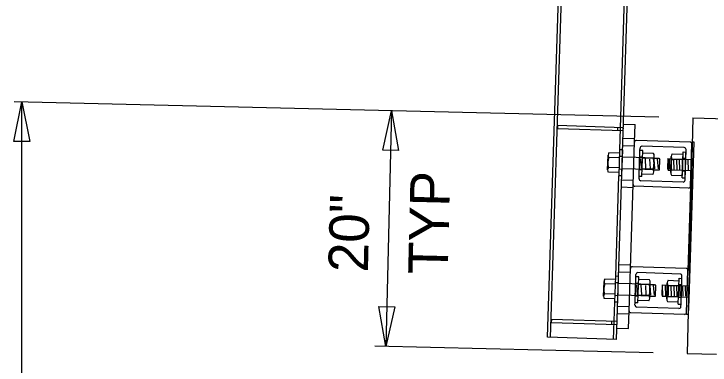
# Model space of a CAD drawing. Extents: x -86 to 68, y -5 to 62.
# Drawn here: x 7.703 to 12.621, y 25.889 to 28.371 of the extents above; entities that cross this region are included whole.
import ezdxf

# ---------------------------------------------------------------- set-up
doc = ezdxf.new("R2010")
doc.units = 0
for name, color, linetype in [('BR_P_Gen_Text', 7, 'Continuous'), ('BR_P_Rail_Hidden', 7, 'Continuous'), ('BR_P_Rail_Object', 7, 'Continuous'), ('BR_P_Slab_Object', 7, 'Continuous'), ('TX_P_1', 7, 'Continuous')]:
    doc.layers.add(name, color=color, linetype=linetype)

msp = doc.modelspace()

# ---------------------------------------------------------------- linework, layer by layer
at = {"layer": 'BR_P_Gen_Text'}
for points in [[(7.8153, 27.4694), (7.7033, 27.4694), (7.7593, 27.7494)], [(10.4206, 27.4054), (10.3087, 27.4081), (10.3714, 27.6867)], [(10.2821, 26.3022), (10.3941, 26.2995), (10.3314, 26.021)]]:
    msp.add_lwpolyline(points, close=True, dxfattribs=at)
at = {"layer": 'BR_P_Rail_Hidden'}
for p, q in [((12.0099, 27.5921), (12.0911, 27.5895)), ((12.0871, 27.4643), (12.0911, 27.5895)), ((12.0878, 27.488), (12.0066, 27.4906)), ((12.0862, 27.4372), (12.005, 27.4398)), ((12.0025, 27.3637), (11.9822, 27.3643)), ((12.098, 27.3564), (12.0024, 27.3595)), ((12.2267, 27.3523), (12.098, 27.3564)), ((12.1216, 27.2726), (12.1242, 27.3556)), ((12.1447, 27.3591), (12.1244, 27.3598)), ((12.1361, 27.2798), (12.1325, 27.3477)), ((12.1677, 27.2788), (12.1641, 27.3467)), ((12.1993, 27.2778), (12.1957, 27.3456)), ((12.4492, 27.3494), (12.4289, 27.35)), ((11.9996, 27.2723), (11.9793, 27.273)), ((12.0953, 27.2734), (11.9998, 27.2765)), ((12.2241, 27.2693), (12.0953, 27.2734)), ((12.1417, 27.2678), (12.1214, 27.2684)), ((12.4463, 27.258), (12.426, 27.2587)), ((12.0784, 27.1936), (11.9972, 27.1962)), ((12.0585, 26.571), (12.0775, 27.1665)), ((12.0768, 27.1428), (11.9956, 27.1454)), ((12.0592, 26.5947), (11.978, 26.5973)), ((12.0576, 26.5439), (11.9764, 26.5465)), ((11.974, 26.4704), (11.9537, 26.471)), ((12.0694, 26.4631), (11.9738, 26.4662)), ((12.1981, 26.459), (12.0694, 26.4631)), ((12.093, 26.3793), (12.0956, 26.4623)), ((12.1161, 26.4658), (12.0958, 26.4665)), ((12.1076, 26.3865), (12.1039, 26.4544)), ((12.1391, 26.3855), (12.1355, 26.4534)), ((12.1707, 26.3845), (12.1671, 26.4524)), ((12.4206, 26.4561), (12.4003, 26.4567)), ((11.971, 26.379), (11.9507, 26.3797)), ((12.0668, 26.3801), (11.9712, 26.3832)), ((12.1955, 26.376), (12.0668, 26.3801)), ((12.1132, 26.3745), (12.0928, 26.3751)), ((12.4177, 26.3647), (12.3974, 26.3654)), ((12.0498, 26.3003), (11.9686, 26.3029)), ((12.0449, 26.148), (12.0489, 26.2732)), ((12.0482, 26.2495), (11.967, 26.2521)), ((11.9637, 26.1506), (12.0449, 26.148))]:
    msp.add_line(p, q, dxfattribs=at)
at = {"layer": 'BR_P_Rail_Object'}
for p, q in [((11.4739, 26.085), (11.6142, 30.4703)), ((11.9829, 27.41), (12.0804, 30.4553)), ((11.495, 26.0843), (11.6171, 29.9011)), ((11.9611, 26.0694), (12.0435, 28.6444)), ((11.9684, 27.568), (11.9678, 27.5477)), ((12.0775, 27.1665), (12.0871, 27.4643)), ((12.48, 27.4652), (12.101, 27.4774)), ((12.4731, 26.3515), (12.5088, 27.4643)), ((12.4836, 27.1533), (12.4931, 27.4513)), ((12.4935, 27.4648), (12.4931, 27.4513)), ((12.5088, 27.4643), (12.4935, 27.4648)), ((11.9779, 27.2273), (11.9837, 27.41)), ((12.004, 27.4093), (11.9837, 27.41)), ((11.9982, 27.2266), (12.004, 27.4093)), ((12.12, 27.2227), (12.1258, 27.4055)), ((12.1258, 27.4055), (12.1264, 27.4224)), ((12.1461, 27.4048), (12.1258, 27.4055)), ((12.4381, 27.4259), (12.1403, 27.4355)), ((12.1403, 27.2221), (12.1461, 27.4048)), ((12.4245, 27.213), (12.4304, 27.3957)), ((12.4304, 27.3957), (12.4507, 27.3951)), ((12.4443, 27.1954), (12.4512, 27.412)), ((12.4448, 27.2123), (12.4507, 27.3951)), ((11.8976, 27.2689), (11.9009, 27.3736)), ((11.9819, 27.3547), (11.9058, 27.3572)), ((11.983, 27.3872), (11.9069, 27.3896)), ((12.2212, 27.3482), (12.1444, 27.3507)), ((12.2224, 27.3854), (12.1456, 27.3879)), ((12.2236, 27.255), (12.2272, 27.3666)), ((12.2267, 27.3523), (12.2584, 27.3513)), ((12.2309, 27.2768), (12.2273, 27.3446)), ((12.2584, 27.3513), (12.266, 27.339)), ((12.3221, 27.3484), (12.32, 27.2803)), ((12.3221, 27.3484), (12.3246, 27.267)), ((12.3221, 27.3484), (12.3465, 27.3476)), ((12.3435, 27.2511), (12.347, 27.3628)), ((12.3465, 27.3476), (12.5049, 27.3425)), ((12.353, 27.3812), (12.4298, 27.3788)), ((12.4298, 27.3788), (12.425, 27.2299)), ((12.2571, 27.2759), (12.2498, 27.3439)), ((12.2637, 27.268), (12.266, 27.339)), ((12.3325, 27.3413), (12.3346, 27.2734)), ((12.3519, 27.344), (12.4286, 27.3416)), ((12.363, 27.3403), (12.365, 27.2725)), ((12.3833, 27.3396), (12.3853, 27.2718)), ((12.4036, 27.339), (12.4056, 27.2712)), ((12.4239, 27.3383), (12.4259, 27.2705)), ((12.4442, 27.3377), (12.4462, 27.2699)), ((12.4645, 27.337), (12.4665, 27.2692)), ((12.4848, 27.3364), (12.4868, 27.2686)), ((11.9786, 27.2501), (11.9025, 27.2525)), ((11.9796, 27.2826), (11.9035, 27.285)), ((12.2188, 27.2738), (12.142, 27.2762)), ((12.2241, 27.2693), (12.2637, 27.268)), ((12.32, 27.2803), (12.3246, 27.267)), ((12.3246, 27.267), (12.3439, 27.2664)), ((12.5023, 27.2613), (12.3439, 27.2664)), ((12.3495, 27.2696), (12.4262, 27.2671)), ((11.9543, 26.5167), (11.977, 27.2273)), ((11.9982, 27.2266), (11.9779, 27.2273)), ((12.1194, 27.2058), (12.12, 27.2227)), ((12.1403, 27.2221), (12.12, 27.2227)), ((12.2176, 27.2365), (12.1408, 27.239)), ((12.3483, 27.2324), (12.425, 27.2299)), ((12.4245, 27.213), (12.4448, 27.2123)), ((12.4696, 27.1404), (12.0906, 27.1525)), ((12.4303, 27.1823), (12.1325, 27.1918)), ((12.4836, 27.1535), (12.4645, 26.558)), ((12.0489, 26.2732), (12.0585, 26.571)), ((12.4514, 26.572), (12.0724, 26.5841)), ((12.455, 26.2602), (12.4645, 26.558)), ((11.9493, 26.334), (11.9551, 26.5167)), ((11.9754, 26.5161), (11.9551, 26.5167)), ((11.9696, 26.3333), (11.9754, 26.5161)), ((12.0914, 26.3294), (12.0972, 26.5122)), ((12.0972, 26.5122), (12.0978, 26.5291)), ((12.1175, 26.5115), (12.0972, 26.5122)), ((12.4095, 26.5326), (12.1117, 26.5422)), ((12.1117, 26.3288), (12.1175, 26.5115)), ((12.4221, 26.5018), (12.4226, 26.5187)), ((11.869, 26.3756), (11.8723, 26.4803)), ((11.9534, 26.4614), (11.8772, 26.4639)), ((11.9544, 26.4939), (11.8783, 26.4963)), ((12.1938, 26.4921), (12.117, 26.4946)), ((12.195, 26.3617), (12.1986, 26.4733)), ((12.1981, 26.459), (12.2298, 26.458)), ((12.3149, 26.3579), (12.3184, 26.4695)), ((12.3245, 26.488), (12.4012, 26.4855)), ((12.3959, 26.3197), (12.4018, 26.5024)), ((12.4018, 26.5024), (12.4221, 26.5018)), ((12.4162, 26.319), (12.4221, 26.5018)), ((12.1926, 26.4549), (12.1158, 26.4574)), ((12.2023, 26.3835), (12.1987, 26.4513)), ((12.2285, 26.3826), (12.2213, 26.4506)), ((12.2298, 26.458), (12.2374, 26.4457)), ((12.2351, 26.3748), (12.2374, 26.4457)), ((12.2834, 26.4554), (12.2812, 26.3874)), ((12.2834, 26.4554), (12.318, 26.4543)), ((12.2836, 26.4486), (12.2857, 26.3808)), ((12.3039, 26.448), (12.306, 26.3801)), ((12.318, 26.4543), (12.4763, 26.4492)), ((12.3233, 26.4507), (12.4, 26.4483)), ((12.3242, 26.4473), (12.3263, 26.3795)), ((12.3445, 26.4467), (12.3466, 26.3788)), ((12.3648, 26.446), (12.3669, 26.3782)), ((12.3851, 26.4454), (12.3872, 26.3775)), ((12.4054, 26.4447), (12.4075, 26.3769)), ((12.4257, 26.4441), (12.4278, 26.3762)), ((12.446, 26.4434), (12.4481, 26.3756)), ((12.4663, 26.4428), (12.4684, 26.3749)), ((11.951, 26.3893), (11.8749, 26.3917)), ((12.1902, 26.3805), (12.1134, 26.3829)), ((12.1955, 26.376), (12.2351, 26.3748)), ((12.2812, 26.3874), (12.2859, 26.374)), ((12.3154, 26.3731), (12.2859, 26.374)), ((12.3154, 26.3731), (12.4737, 26.368)), ((12.3209, 26.3763), (12.3977, 26.3738)), ((11.95, 26.3568), (11.8739, 26.3592)), ((11.94, 26.0701), (11.9485, 26.334)), ((11.9696, 26.3333), (11.9493, 26.334)), ((12.0908, 26.3125), (12.0914, 26.3294)), ((12.1117, 26.3288), (12.0914, 26.3294)), ((12.189, 26.3433), (12.1122, 26.3457)), ((12.3197, 26.3391), (12.3965, 26.3366)), ((12.3959, 26.3197), (12.4162, 26.319)), ((12.4157, 26.3021), (12.4162, 26.319)), ((12.4698, 26.2462), (12.4731, 26.3515)), ((12.4017, 26.289), (12.1039, 26.2986)), ((12.441, 26.2471), (12.062, 26.2592)), ((12.4546, 26.2467), (12.455, 26.2602)), ((12.4698, 26.2462), (12.4546, 26.2467)), ((11.9246, 26.1976), (11.9239, 26.1773)), ((11.9611, 26.0694), (11.4739, 26.085))]:
    msp.add_line(p, q, dxfattribs=at)
for points in [[(11.5431, 27.5613), (12.0084, 27.5464), (12.009, 27.5667), (11.5437, 27.5816)], [(11.4992, 26.1909), (11.9645, 26.176), (11.9652, 26.1963), (11.4999, 26.2112)]]:
    msp.add_lwpolyline(points, close=True, dxfattribs=at)
for centre, radius, start, end in [((12.1006, 27.4638), 0.0135, 88.167, 178.167), ((12.4796, 27.4517), 0.0135, 358.167, 88.167), ((12.1399, 27.4219), 0.0135, 88.167, 178.167), ((12.4377, 27.4124), 0.0135, 358.167, 88.167), ((12.0222, 27.3173), 0.123, 161.1012, 195.2327), ((11.928, 27.3727), 0.0271, 141.2971, 215.0369), ((12.0947, 27.315), 0.1307, 341.6152, 14.7188), ((12.1925, 27.3678), 0.0347, 325.7266, 30.6074), ((12.3817, 27.3617), 0.0347, 145.7266, 210.6074), ((12.4759, 27.3028), 0.1307, 161.6152, 194.7188), ((11.9246, 27.2681), 0.0271, 141.2971, 215.0369), ((12.1889, 27.2561), 0.0347, 325.7266, 30.6074), ((12.3782, 27.25), 0.0347, 145.7266, 210.6074), ((12.133, 27.2054), 0.0135, 178.167, 268.167), ((12.0911, 27.1661), 0.0135, 178.167, 268.167), ((12.4307, 27.1959), 0.0135, 268.167, 358.167), ((12.47, 27.1539), 0.0135, 268.167, 358.167), ((12.072, 26.5705), 0.0135, 88.167, 178.167), ((12.451, 26.5584), 0.0135, 358.167, 88.167), ((12.1113, 26.5286), 0.0135, 88.167, 178.167), ((12.4091, 26.5191), 0.0135, 358.167, 88.167), ((11.9936, 26.424), 0.123, 161.1012, 195.2327), ((11.8994, 26.4794), 0.0271, 141.2971, 215.0369), ((12.1639, 26.4745), 0.0347, 325.7266, 30.6074), ((12.3531, 26.4684), 0.0347, 145.7266, 210.6074), ((12.0661, 26.4217), 0.1307, 341.6152, 14.7188), ((12.4473, 26.4095), 0.1307, 161.6152, 194.7188), ((11.8961, 26.3748), 0.0271, 141.2971, 215.0369), ((12.1603, 26.3628), 0.0347, 325.7266, 30.6074), ((12.3496, 26.3567), 0.0347, 145.7266, 210.6074), ((12.1044, 26.3121), 0.0135, 178.167, 268.167), ((12.0625, 26.2728), 0.0135, 178.167, 268.167), ((12.4021, 26.3026), 0.0135, 268.167, 358.167), ((12.4414, 26.2607), 0.0135, 268.167, 358.167)]:
    msp.add_arc(centre, radius, start, end, dxfattribs=at)
at = {"layer": 'BR_P_Slab_Object'}
for p, q in [((12.499, 27.6356), (12.459, 25.9699)), ((12.499, 27.6356), (54.499, 26.6276)), ((12.459, 25.9699), (12.6673, 25.9649))]:
    msp.add_line(p, q, dxfattribs=at)
at = {"layer": 'TX_P_1'}
for p, q in [((12.2597, 27.6413), (7.704, 27.7507)), ((7.7593, 25.338), (7.7593, 27.7494)), ((10.3714, 27.6867), (10.3314, 26.021)), ((12.2197, 25.9756), (10.2537, 26.0228))]:
    msp.add_line(p, q, dxfattribs=at)

# ---------------------------------------------------------------- texts
for s, p in [('TYP', (10.7679, 26.5276)), ('20"', (10.2039, 26.5423))]:
    msp.add_text(s, height=0.28, rotation=88.6252, dxfattribs=at).set_placement(p)

doc.saveas('drawing.dxf')
